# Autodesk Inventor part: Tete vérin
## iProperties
Shininess: 20.0
Angle Display Precision: 2
Document Length Units: 11269
Document Angle Units: 11279
Document Time Units: 11290
Document Mass Units: 11283
Document Length Units Precision: 3
Document Angle Units Precision: 2
Created: 2002-09
Part Number: Tete vérin
Material: Par défaut
Document SubType Name: Modélisation
Designer: administrateur
Density: 0.0
Volumn: 0.0
Area: 0.0
PropertySet Name: Model Information
Control State: 0
Master: False
Checked Out: False
Author: administrateur
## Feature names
1. Extrusion1
2. Chanfrein1 [Chamfer]
3. Chanfrein2 [Chamfer]
4. Extrusion2
5. Extrusion3
6. Symétrie1 [Mirror]
7. Symétrie2 [Mirror]
8. Réseau circulaire1 [Circular Pattern]
9. Symétrie3 [Mirror]
10. Symétrie4 [Mirror]
11. Extrusion4
12. Réseau circulaire2 [Circular Pattern]
13. Extrusion5
14. Extrusion6
15. Chanfrein3 [Chamfer]
16. Réseau circulaire3 [Circular Pattern]
17. Congé1 [Fillet]
18. Congé2 [Fillet]
19. Congé3 [Fillet]
20. Congé4 [Fillet]
21. Congé5 [Fillet]
22. Extrusion7
23. Extrusion8
